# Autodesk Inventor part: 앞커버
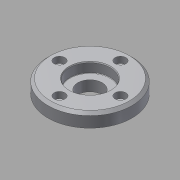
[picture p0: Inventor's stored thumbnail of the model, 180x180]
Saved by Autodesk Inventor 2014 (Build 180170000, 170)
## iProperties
Created: 2015-09
Part Number: 앞커버
Material: 알루미늄 6061
Document SubType Name: Modeling
Designer: mduedu
Density: 1 g/cm^3
Appearance: Aluminum - Flat
Author: mduedu
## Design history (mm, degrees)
sketch "스케치1"
  geometry: L1 (0, 7.5)-(0, -7.5); L2 (0, 7.5)-(31, 7.5); L3 (31, 7.5)-(31, -2.5); L4 (31, -2.5)-(17.5, -2.5); L5 (17.5, -2.5)-(17.5, -7.5); L6 (17.5, -7.5)-(0, -7.5); 2 further points
  constraints: 12 end point, 2 parallel, 2 perpendicular, 1 coincident, 1 horizontal, 1 midpoint, 1 vertical
  dimensions: "d0" = 15 distance of L1.start L1.end; "d1" = 62 diameter of L3 L1; "d2" = 35 diameter of L5 L1; "d3" = 10 distance of L2.end L3.end
revolve "회전1" sketch "스케치1" stored, may be unused: angle "d4" = 90 deg
hole "구멍1" diameter "d7" = 30; stored, may be unused: countersink angle "d11" = 90 deg, drill point angle "d13" = 0 deg; dims "d5" = 10, "d6" = 10, "d8" = 6, "d9" = 4, "d10" = 2, "d12" = 7.3
hole "구멍2" diameter "d16" = 18; stored, may be unused: countersink angle "d20" = 90 deg, drill point angle "d22" = 0 deg; dims "d14" = 10, "d15" = 10, "d17" = 6, "d18" = 4, "d19" = 2, "d21" = 7.3
chamfer "모따기1" distance "d23" = 2; stored, may be unused: second distance "d24" = 2, angle "d25" = 45 deg
chamfer "모따기2" distance "d26" = 0.7; stored, may be unused: second distance "d27" = 2, angle "d28" = 30 deg
fillet "모깎기1" dims "d29" = 0.3
sketch "스케치2" dims "d30" = 45
  geometry: 6 further points
  constraints: 2 vertical alignment, 1 coincident, 7 other
  dimensions: "d34" = 360 deg dimension on point (0, 0) point (0, 22.5) (derived)
sketch "스케치3"
  geometry: 4 further points
hole "구멍3" sketch "스케치3" at (0, 22.5), (-22.5, 0), (22.5, 0), (0, -22.5) diameter "d36" = 4.5; stored, may be unused: countersink angle "d40" = 90 deg, drill point angle "d42" = 0 deg; dims "d37" = 6, "d38" = 8, "d39" = 4.6, "d41" = 8
node "솔리드1"
